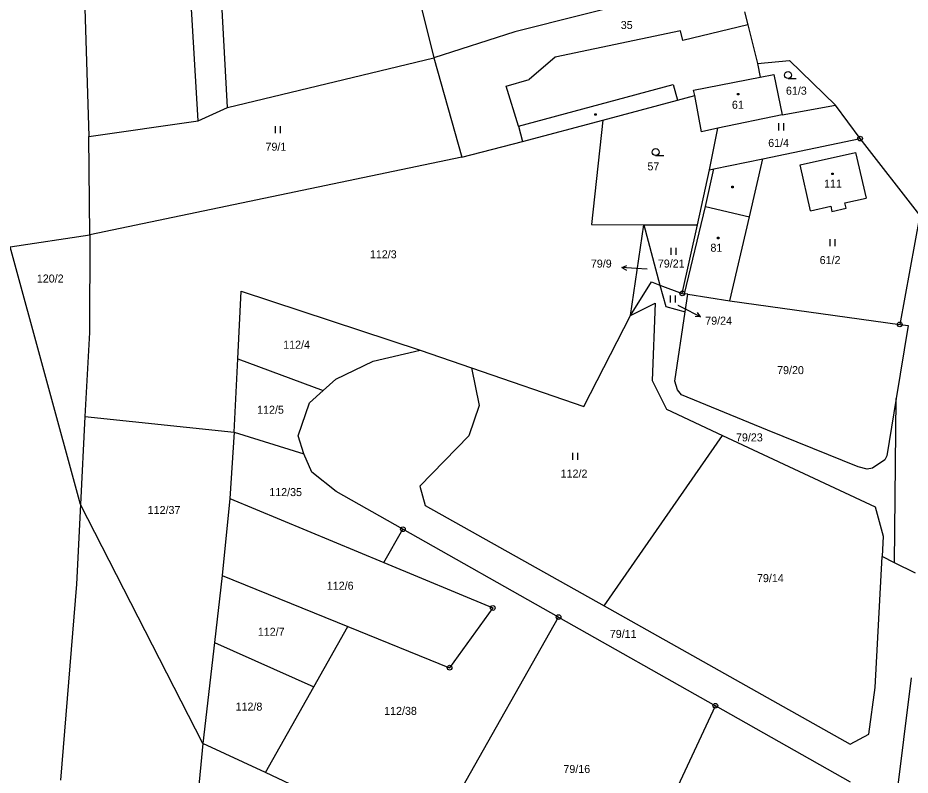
# Model space of a CAD drawing. Extents: x -794142 to -791199, y -1109267 to -1105626.
# Drawn here: x -793649.2 to -793459.6, y -1107988.9 to -1107828.1 of the extents above; entities that cross this region are included whole.
import ezdxf

# ---------------------------------------------------------------- set-up
doc = ezdxf.new("R2010")
doc.units = 0
for name, color, linetype in [('Komunikace', 7, 'Continuous'), ('Vrstva 1', 7, 'Continuous'), ('Vrstva 14', 7, 'Continuous'), ('Vrstva 15', 7, 'Continuous'), ('Vrstva 16', 7, 'Continuous'), ('Vrstva 2', 7, 'Continuous'), ('Vrstva 23', 7, 'Continuous'), ('Vrstva 25', 7, 'Continuous'), ('Vrstva 28', 7, 'Continuous')]:
    doc.layers.add(name, color=color, linetype=linetype)

msp = doc.modelspace()

# ---------------------------------------------------------------- linework, layer by layer
at = {"layer": 'Komunikace'}
for p, q in [((-793515.45, -1107881.48), (-793517.83, -1107881.32)), ((-793508.95, -1107889.07), (-793506.81, -1107890.18))]:
    msp.add_line(p, q, dxfattribs=at)
at = {"layer": 'Vrstva 1'}
for p, q in [((-793635.53, -1107808.45), (-793634.1, -1107853.25)), ((-793604.64, -1107847.08), (-793606.65, -1107809.95)), ((-793610.84, -1107849.94), (-793613.14, -1107811.81)), ((-793498.31, -1107819.6), (-793543.6, -1107831.04)), ((-793564.77, -1107820.47), (-793560.8, -1107836.53)), ((-793494.79, -1107826.79), (-793494.12, -1107829.52)), ((-793494.12, -1107829.52), (-793492.03, -1107837.73)), ((-793543.6, -1107831.04), (-793560.8, -1107836.53)), ((-793604.64, -1107847.08), (-793560.8, -1107836.53)), ((-793560.8, -1107836.53), (-793554.84, -1107857.69)), ((-793492.03, -1107837.73), (-793485.27, -1107837.13)), ((-793485.27, -1107837.13), (-793475.45, -1107846.63)), ((-793492.03, -1107837.73), (-793491.46, -1107840.68)), ((-793505.66, -1107843.42), (-793491.46, -1107840.68)), ((-793491.46, -1107840.68), (-793488.58, -1107840.12)), ((-793488.58, -1107840.12), (-793486.77, -1107848.7)), ((-793509.06, -1107845.52), (-793505.38, -1107844.53)), ((-793505.38, -1107844.53), (-793505.66, -1107843.42)), ((-793503.91, -1107852.25), (-793505.38, -1107844.53)), ((-793524.91, -1107849.77), (-793509.06, -1107845.52)), ((-793486.77, -1107848.7), (-793475.45, -1107846.63)), ((-793470.25, -1107853.7), (-793475.45, -1107846.63)), ((-793610.84, -1107849.94), (-793604.64, -1107847.08)), ((-793634.1, -1107853.25), (-793610.84, -1107849.94)), ((-793541.99, -1107854.31), (-793524.91, -1107849.77)), ((-793524.91, -1107849.77), (-793527.29, -1107871.96)), ((-793486.77, -1107848.7), (-793500.43, -1107851.47)), ((-793500.43, -1107851.47), (-793503.91, -1107852.25)), ((-793502.22, -1107860.36), (-793500.43, -1107851.47)), ((-793633.91, -1107874.16), (-793634.1, -1107853.25)), ((-793554.84, -1107857.69), (-793541.99, -1107854.31)), ((-793490.91, -1107857.99), (-793470.25, -1107853.7)), ((-793457.57, -1107869.96), (-793470.25, -1107853.7)), ((-793554.84, -1107857.69), (-793633.91, -1107874.16)), ((-793501.31, -1107860.17), (-793490.91, -1107857.99)), ((-793493.76, -1107870.3), (-793490.91, -1107857.99)), ((-793483, -1107859.3), (-793471.2, -1107856.65)), ((-793471.2, -1107856.65), (-793468.92, -1107866.34)), ((-793480.75, -1107869.07), (-793483, -1107859.3)), ((-793504.8, -1107872.05), (-793502.22, -1107860.36)), ((-793502.22, -1107860.36), (-793501.31, -1107860.17)), ((-793473.49, -1107867.39), (-793468.92, -1107866.34)), ((-793473.23, -1107868.52), (-793473.49, -1107867.39)), ((-793480.75, -1107869.07), (-793476.47, -1107868.08)), ((-793476.47, -1107868.08), (-793476.21, -1107869.2)), ((-793476.21, -1107869.2), (-793473.23, -1107868.52)), ((-793497.9, -1107888.17), (-793493.76, -1107870.3)), ((-793457.57, -1107869.96), (-793461.81, -1107893.18)), ((-793527.29, -1107871.96), (-793516.15, -1107872)), ((-793519.05, -1107891.31), (-793516.15, -1107872)), ((-793516.15, -1107872), (-793512.75, -1107884.84)), ((-793516.15, -1107872), (-793504.8, -1107872.05)), ((-793508.01, -1107886.6), (-793504.8, -1107872.05)), ((-793650.8, -1107876.74), (-793633.91, -1107874.16)), ((-793633.91, -1107874.16), (-793633.93, -1107894.92)), ((-793635.87, -1107931.43), (-793650.8, -1107876.74)), ((-793519.05, -1107891.31), (-793514.54, -1107884.17)), ((-793514.54, -1107884.17), (-793512.75, -1107884.84)), ((-793602.45, -1107900.49), (-793601.76, -1107886.11)), ((-793601.76, -1107886.11), (-793563.72, -1107898.66)), ((-793512.75, -1107884.84), (-793511.54, -1107889.41)), ((-793512.75, -1107884.84), (-793508.01, -1107886.6)), ((-793508.01, -1107886.6), (-793507.57, -1107886.66)), ((-793506.81, -1107886.78), (-793507.57, -1107886.66)), ((-793507.37, -1107890.51), (-793506.81, -1107886.78)), ((-793506.81, -1107886.78), (-793497.9, -1107888.17)), ((-793497.9, -1107888.17), (-793461.81, -1107893.18)), ((-793519.05, -1107891.31), (-793513.76, -1107888.64)), ((-793513.76, -1107888.64), (-793514.38, -1107905.13)), ((-793511.54, -1107889.41), (-793507.37, -1107890.51)), ((-793528.95, -1107910.63), (-793519.05, -1107891.31)), ((-793509.59, -1107905.25), (-793507.37, -1107890.51)), ((-793460.04, -1107893.43), (-793462.55, -1107908.91)), ((-793461.81, -1107893.18), (-793460.04, -1107893.43)), ((-793633.93, -1107894.92), (-793634.97, -1107912.76)), ((-793573.69, -1107901.01), (-793563.72, -1107898.66)), ((-793563.72, -1107898.66), (-793552.79, -1107902.43)), ((-793603.2, -1107916.1), (-793602.45, -1107900.49)), ((-793602.45, -1107900.49), (-793584.29, -1107907.22)), ((-793581.6, -1107904.82), (-793573.69, -1107901.01)), ((-793552.79, -1107902.43), (-793551.17, -1107910.41)), ((-793552.79, -1107902.43), (-793528.95, -1107910.63)), ((-793584.29, -1107907.22), (-793581.6, -1107904.82)), ((-793514.38, -1107905.13), (-793511.34, -1107911.22)), ((-793509.03, -1107907.1), (-793509.59, -1107905.25)), ((-793587.24, -1107909.85), (-793584.29, -1107907.22)), ((-793508.19, -1107908.15), (-793509.03, -1107907.1)), ((-793489.93, -1107915.68), (-793508.19, -1107908.15)), ((-793462.55, -1107908.91), (-793464.53, -1107921.1)), ((-793462.94, -1107943.85), (-793462.55, -1107908.91)), ((-793589.61, -1107916.84), (-793587.24, -1107909.85)), ((-793551.17, -1107910.41), (-793553.39, -1107916.85)), ((-793511.34, -1107911.22), (-793499.46, -1107916.77)), ((-793634.97, -1107912.76), (-793635.87, -1107931.43)), ((-793634.97, -1107912.76), (-793603.2, -1107916.1)), ((-793603.2, -1107916.1), (-793604.15, -1107930.15)), ((-793603.2, -1107916.1), (-793588.44, -1107920.65)), ((-793588.44, -1107920.65), (-793589.61, -1107916.84)), ((-793563.78, -1107927.58), (-793553.39, -1107916.85)), ((-793524.61, -1107952.97), (-793499.46, -1107916.77)), ((-793499.46, -1107916.77), (-793467.03, -1107931.94)), ((-793470.67, -1107923.47), (-793489.93, -1107915.68)), ((-793586.75, -1107924.55), (-793588.44, -1107920.65)), ((-793464.95, -1107921.97), (-793467.58, -1107923.76)), ((-793464.53, -1107921.1), (-793464.95, -1107921.97)), ((-793468.76, -1107923.92), (-793470.67, -1107923.47)), ((-793467.58, -1107923.76), (-793468.76, -1107923.92)), ((-793581.55, -1107928.68), (-793586.75, -1107924.55)), ((-793563.78, -1107927.58), (-793562.63, -1107931.65)), ((-793604.15, -1107930.15), (-793605.74, -1107946.53)), ((-793604.15, -1107930.15), (-793571.39, -1107943.8)), ((-793567.38, -1107936.69), (-793581.55, -1107928.68)), ((-793635.87, -1107931.43), (-793636.68, -1107948.35)), ((-793609.89, -1107982.22), (-793635.87, -1107931.43)), ((-793562.63, -1107931.65), (-793524.61, -1107952.97)), ((-793467.03, -1107931.94), (-793465.34, -1107938.19)), ((-793571.39, -1107943.8), (-793567.38, -1107936.69)), ((-793534.31, -1107955.37), (-793567.38, -1107936.69)), ((-793465.34, -1107938.19), (-793465.56, -1107942.48)), ((-793467.05, -1107970.31), (-793465.56, -1107942.48)), ((-793462.94, -1107943.85), (-793465.56, -1107942.48)), ((-793571.39, -1107943.8), (-793548.27, -1107953.43)), ((-793458.47, -1107946.04), (-793462.94, -1107943.85)), ((-793605.74, -1107946.53), (-793607.41, -1107960.79)), ((-793605.74, -1107946.53), (-793579.05, -1107957.35)), ((-793636.68, -1107948.35), (-793640.1, -1107990)), ((-793548.27, -1107953.43), (-793557.44, -1107966.11)), ((-793524.61, -1107952.97), (-793472.37, -1107982.36)), ((-793562.05, -1108004.47), (-793534.31, -1107955.37)), ((-793534.31, -1107955.37), (-793500.99, -1107974.19)), ((-793586.3, -1107970.18), (-793579.05, -1107957.35)), ((-793579.05, -1107957.35), (-793557.44, -1107966.11)), ((-793607.41, -1107960.79), (-793609.89, -1107982.22)), ((-793607.41, -1107960.79), (-793586.3, -1107970.18)), ((-793459.42, -1107968.29), (-793461.03, -1107981.37)), ((-793596.59, -1107988.41), (-793586.3, -1107970.18)), ((-793468.37, -1107980.26), (-793467.05, -1107970.31)), ((-793523.03, -1108021.45), (-793500.99, -1107974.19)), ((-793472.28, -1107990.41), (-793500.99, -1107974.19)), ((-793472.37, -1107982.36), (-793468.37, -1107980.26)), ((-793461.03, -1107981.37), (-793462.96, -1107997.07)), ((-793609.89, -1107982.22), (-793611.09, -1107995.15)), ((-793596.59, -1107988.41), (-793609.89, -1107982.22)), ((-793569.72, -1108000.92), (-793596.59, -1107988.41))]:
    msp.add_line(p, q, dxfattribs=at)
at = {"layer": 'Vrstva 16'}
for p, q in [((-793520.823, -1107881.119), (-793519.792, -1107880.687)), ((-793517.83, -1107881.32), (-793520.823, -1107881.119)), ((-793520.823, -1107881.119), (-793519.858, -1107881.685)), ((-793506.81, -1107890.18), (-793504.143, -1107891.554)), ((-793504.143, -1107891.554), (-793505.261, -1107891.54)), ((-793504.143, -1107891.554), (-793504.803, -1107890.652))]:
    msp.add_line(p, q, dxfattribs=at)
at = {"layer": 'Vrstva 2'}
for p, q in [((-793494.12, -1107829.52), (-793507.88, -1107832.88)), ((-793508.39, -1107830.85), (-793535.03, -1107836.44)), ((-793507.88, -1107832.88), (-793508.39, -1107830.85)), ((-793535.03, -1107836.44), (-793540.52, -1107841.19)), ((-793545.43, -1107842.59), (-793540.52, -1107841.19)), ((-793542.83, -1107851.07), (-793545.43, -1107842.59)), ((-793542.83, -1107851.07), (-793509.95, -1107842.22)), ((-793509.95, -1107842.22), (-793509.06, -1107845.52)), ((-793542.83, -1107851.07), (-793541.99, -1107854.31)), ((-793503.08, -1107868.14), (-793501.31, -1107860.17)), ((-793507.57, -1107886.66), (-793503.08, -1107868.14)), ((-793503.08, -1107868.14), (-793493.76, -1107870.3))]:
    msp.add_line(p, q, dxfattribs=at)
at = {"layer": 'Vrstva 23'}
for p, q in [((-793485.54, -1107840.97), (-793483.79, -1107840.97)), ((-793487.49, -1107851.96), (-793487.49, -1107850.46)), ((-793486.49, -1107850.46), (-793486.49, -1107851.96)), ((-793594.41, -1107852.59), (-793594.41, -1107851.09)), ((-793593.41, -1107851.09), (-793593.41, -1107852.59)), ((-793513.67, -1107857.32), (-793511.92, -1107857.32)), ((-793476.57, -1107876.55), (-793476.57, -1107875.05)), ((-793475.57, -1107875.05), (-793475.57, -1107876.55)), ((-793510.4, -1107878.41), (-793510.4, -1107876.91)), ((-793509.4, -1107876.91), (-793509.4, -1107878.41)), ((-793510.55, -1107888.54), (-793510.55, -1107887.04)), ((-793509.55, -1107887.04), (-793509.55, -1107888.54)), ((-793531.26, -1107921.99), (-793531.26, -1107920.49)), ((-793530.26, -1107920.49), (-793530.26, -1107921.99))]:
    msp.add_line(p, q, dxfattribs=at)
for centre in [(-793485.54, -1107840.22), (-793513.67, -1107856.57)]:
    msp.add_circle(centre, 0.75, dxfattribs=at)
at = {"layer": 'Vrstva 25'}
for p, q in [((-793496.29, -1107844.14), (-793495.99, -1107844.14)), ((-793496.29, -1107844.44), (-793496.29, -1107844.14)), ((-793495.99, -1107844.44), (-793496.29, -1107844.44)), ((-793495.99, -1107844.14), (-793495.99, -1107844.44)), ((-793526.61, -1107848.42), (-793526.31, -1107848.42)), ((-793526.61, -1107848.72), (-793526.61, -1107848.42)), ((-793526.31, -1107848.42), (-793526.31, -1107848.72)), ((-793526.31, -1107848.72), (-793526.61, -1107848.72)), ((-793476.23, -1107861.07), (-793475.93, -1107861.07)), ((-793476.23, -1107861.37), (-793476.23, -1107861.07)), ((-793475.93, -1107861.37), (-793476.23, -1107861.37)), ((-793475.93, -1107861.07), (-793475.93, -1107861.37)), ((-793497.5, -1107863.84), (-793497.2, -1107863.84)), ((-793497.5, -1107864.14), (-793497.5, -1107863.84)), ((-793497.2, -1107863.84), (-793497.2, -1107864.14)), ((-793497.2, -1107864.14), (-793497.5, -1107864.14)), ((-793500.53, -1107874.68), (-793500.23, -1107874.68)), ((-793500.53, -1107874.98), (-793500.53, -1107874.68)), ((-793500.23, -1107874.98), (-793500.53, -1107874.98)), ((-793500.23, -1107874.68), (-793500.23, -1107874.98))]:
    msp.add_line(p, q, dxfattribs=at)
at = {"layer": 'Vrstva 28'}
for centre, radius in [((-793470.25, -1107853.7), 0.5), ((-793470.25, -1107853.7), 0.01), ((-793508.01, -1107886.6), 0.5), ((-793508.01, -1107886.6), 0.01), ((-793461.81, -1107893.18), 0.5), ((-793461.81, -1107893.18), 0.01), ((-793567.38, -1107936.69), 0.5), ((-793567.38, -1107936.69), 0.01), ((-793548.27, -1107953.43), 0.5), ((-793548.27, -1107953.43), 0.01), ((-793534.31, -1107955.37), 0.5), ((-793534.31, -1107955.37), 0.01), ((-793557.44, -1107966.11), 0.5), ((-793557.44, -1107966.11), 0.01), ((-793500.99, -1107974.19), 0.5), ((-793500.99, -1107974.19), 0.01)]:
    msp.add_circle(centre, radius, dxfattribs=at)

# ---------------------------------------------------------------- texts
at = {"layer": 'Vrstva 14'}
for s, height, p in [('61/3', 1.7, (-793485.993, -1107844.39)), ('61/4', 1.7, (-793489.759, -1107855.48)), ('79/1', 1.7, (-793596.56, -1107856.29)), ('57', 1.7, (-793515.42, -1107860.46)), ('112/3', 1.7, (-793574.386, -1107879.14)), ('61/2', 1.7, (-793478.823, -1107880.37)), ('79/21', 1.7, (-793513.2, -1107881.11)), ('120/2', 1.7, (-793645.142, -1107884.29)), ('79/9', 0.1, (-793515.615, -1107881.48)), ('79/24', 0.1, (-793509.157, -1107889.07)), ('112/4', 1.7, (-793592.802, -1107898.35)), ('79/20', 1.7, (-793487.866, -1107903.75)), ('112/5', 1.7, (-793598.343, -1107912.16)), ('79/23', 1.7, (-793496.606, -1107918.04)), ('112/2', 1.7, (-793533.856, -1107925.73)), ('112/35', 1.7, (-793595.762, -1107929.66)), ('112/37', 1.7, (-793621.593, -1107933.47)), ('79/14', 1.7, (-793492.146, -1107947.94)), ('112/6', 1.7, (-793583.536, -1107949.55)), ('112/7', 1.7, (-793598.193, -1107959.33)), ('79/11', 1.7, (-793523.413, -1107959.79)), ('112/8', 1.7, (-793602.916, -1107975.23)), ('112/38', 1.7, (-793571.356, -1107976.14)), ('79/16', 1.7, (-793533.27, -1107988.48))]:
    msp.add_text(s, height=height, dxfattribs=at).set_placement(p)
at = {"layer": 'Vrstva 15'}
for s, p in [('35', (-793521.083, -1107830.43)), ('61', (-793497.47, -1107847.38)), ('111', (-793477.896, -1107864.13)), ('81', (-793502.03, -1107877.75))]:
    msp.add_text(s, height=1.7, dxfattribs=at).set_placement(p)
at = {"layer": 'Vrstva 16'}
for s, p in [('79/9', (-793527.434, -1107881.12)), ('79/24', (-793503.14, -1107893.25))]:
    msp.add_text(s, height=1.7, dxfattribs=at).set_placement(p)

doc.saveas('drawing.dxf')
